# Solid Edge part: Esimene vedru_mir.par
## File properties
Author: Türk
Template: Iso Part.par
Last saved by: Türk
Revision: 2
Application: Solid Edge
Accuracy: 0,990
Username: Türk
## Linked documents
Esimene vedru.par
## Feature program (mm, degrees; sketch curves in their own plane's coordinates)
part copy "CopiedPart_1"
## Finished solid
Body 1: solid body, 7 faces, 18 edges, 12 vertices.
  Faces by surface: plane 4, torus 2, spline 1
  Edges by curve: circle 10, intersection 6, line 2
Bounding box of the edges (mm; curved faces can reach further): 103.000 x 103.000 x 270.000, from (-51.5, -51.5, 0) to (51.5, 51.5, 270).
Toroidal faces (ring radius, tube radius in mm): R45.5 r6 x2
Planar faces by outward normal: +z 1, -z 1, oblique 2
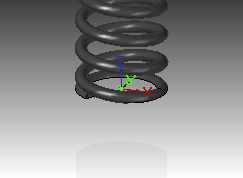
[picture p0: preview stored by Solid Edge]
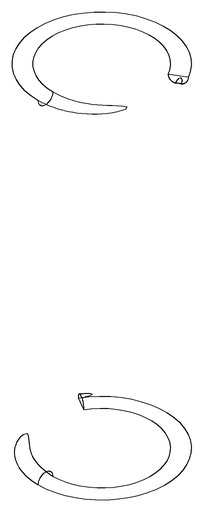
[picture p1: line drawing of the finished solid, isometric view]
